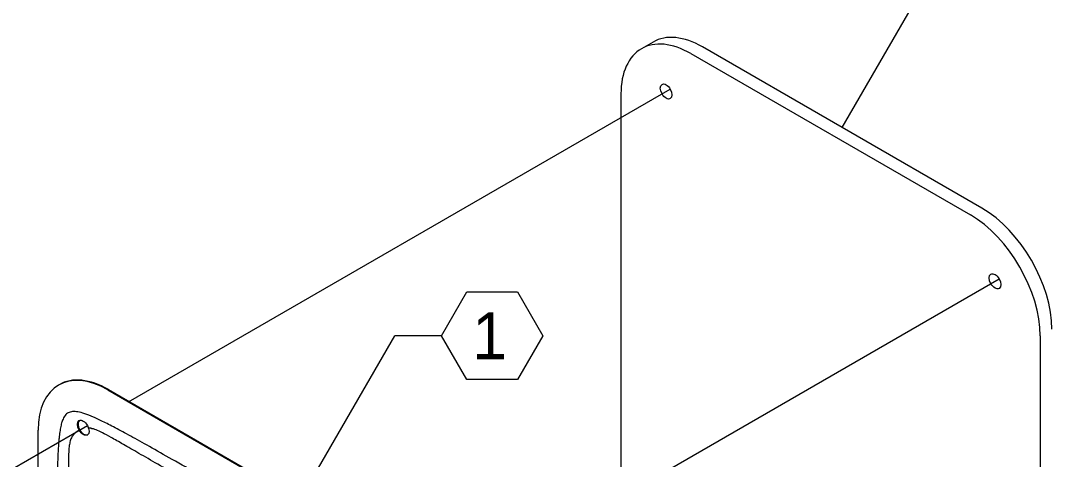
# Model space of a CAD drawing. Extents: x 99862 to 103151, y 100000 to 105076.
# Drawn here: x 100107.4 to 100459.1, y 104683.9 to 104833.8 of the extents above; entities that cross this region are included whole.
import ezdxf

# ---------------------------------------------------------------- set-up
doc = ezdxf.new("R2010")
doc.units = 0
for name, color, linetype in [('Level 15', 7, 'Continuous'), ('Level 16', 7, 'Continuous'), ('Level 20', 7, 'Continuous'), ('Level 40', 7, 'Continuous'), ('Level 41', 7, 'Continuous')]:
    doc.layers.add(name, color=color, linetype=linetype)

msp = doc.modelspace()

# ---------------------------------------------------------------- linework, layer by layer
at = {"layer": 'Level 15'}
for p, q in [((100388.01, 104797.27), (100420.51, 104853.56)), ((100202.67, 104669.82), (100235.17, 104726.11)), ((100251.17, 104726.11), (100235.17, 104726.11))]:
    msp.add_line(p, q, dxfattribs=at)
at = {"layer": 'Level 16'}
for p, q in [((100144.22, 104703.56), (100329.27, 104810.4)), ((100249.76, 104634.79), (100441.6, 104745.55)), ((100058.8, 104654.25), (100130.19, 104695.47))]:
    msp.add_line(p, q, dxfattribs=at)
at = {"layer": 'Level 20'}
msp.add_lwpolyline([(100251.17, 104726.11), (100259.83, 104741.1), (100277.15, 104741.1), (100285.79, 104726.11), (100277.15, 104711.11), (100259.83, 104711.11), (100251.17, 104726.11)], dxfattribs=at)
at = {"layer": 'Level 40'}
for p, q in [((100137.23, 104707.6), (100232.68, 104652.48)), ((100137.42, 104707.71), (100232.88, 104652.6)), ((100113.36, 104463.81), (100113.36, 104693.82))]:
    msp.add_line(p, q, dxfattribs=at)
for centre, major_axis, start_param, end_param in [((100137.23, 104680.04), (-16.88, 29.23), 5.497787, 7.068583), ((100137.42, 104680.16), (-16.88, 29.23), 5.497787, 6.283185), ((100128.99, 104694.77), (-1.41, 2.44), 0.07077, 3.070823)]:
    msp.add_ellipse(centre, major_axis=major_axis, ratio=0.57735, start_param=start_param, end_param=end_param, dxfattribs=at)
msp.add_ellipse((100128.79, 104694.66), major_axis=(-1.41, 2.44), ratio=0.57735, dxfattribs=at)
for points in [[(100231.12, 104642.4), (100183.39, 104669.95), (100135.66, 104697.51), (100119.75, 104706.7), (100119.75, 104688.33), (100119.75, 104573.32), (100119.75, 104458.32), (100119.75, 104439.95), (100135.66, 104430.76), (100183.39, 104403.21), (100231.12, 104375.65), (100247.03, 104366.46), (100247.03, 104384.83), (100247.03, 104499.84), (100247.03, 104614.84), (100247.03, 104621.81), (100243.03, 104629.33)], [(100127.38, 104693.84), (100123.73, 104691.89), (100123.73, 104686.03), (100123.73, 104665.32), (100123.73, 104644.6), (100183.39, 104610.16), (100243.06, 104575.71), (100243.06, 104596.42), (100243.06, 104617.14)], [(100243.06, 104617.14), (100243.06, 104630.92), (100231.12, 104637.81), (100183.39, 104665.36), (100135.66, 104692.92), (100133.01, 104694.45), (100130.6, 104694.54)]]:
    msp.add_open_spline(points, degree=4, dxfattribs=at)
at = {"layer": 'Level 41'}
for p, q in [((100323.4, 104826.5), (100319.42, 104824.2)), ((100336.3, 104822.53), (100431.76, 104767.42)), ((100435.73, 104769.72), (100340.28, 104824.83)), ((100312.43, 104808.75), (100312.43, 104578.75)), ((100455.62, 104726.08), (100455.62, 104496.08))]:
    msp.add_line(p, q, dxfattribs=at)
for centre, start_param, end_param in [((100340.28, 104797.27), 5.497787, 6.283185), ((100336.3, 104794.98), 5.497787, 6.283185), ((100336.3, 104794.98), 6.283185, 7.068583), ((100435.73, 104742.16), 3.926991, 5.497787), ((100431.76, 104739.86), 3.926991, 5.497787)]:
    msp.add_ellipse(centre, major_axis=(-16.88, 29.23), ratio=0.57735, start_param=start_param, end_param=end_param, dxfattribs=at)
for centre in [(100327.86, 104809.59), (100440.19, 104744.73)]:
    msp.add_ellipse(centre, major_axis=(-1.41, 2.44), ratio=0.57735, dxfattribs=at)

# ---------------------------------------------------------------- texts
at = {"layer": 'Level 20'}
msp.add_text('1', height=16, dxfattribs=at).set_placement((100261.62, 104718.11))

doc.saveas('drawing.dxf')
